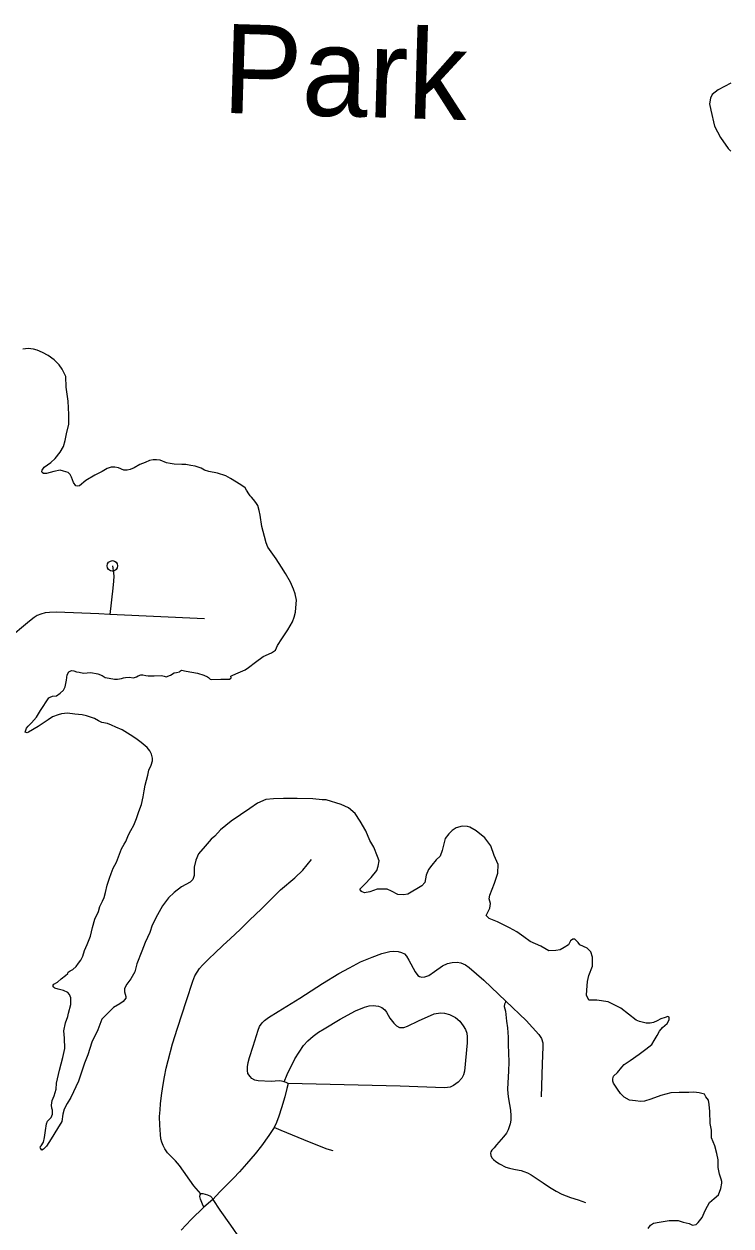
# Model space of a CAD drawing. Extents: x 653372 to 905732, y 627442 to 787275.
# Drawn here: x 725318 to 728673, y 734929 to 740630 of the extents above; entities that cross this region are included whole.
import ezdxf

# ---------------------------------------------------------------- set-up
doc = ezdxf.new("R2010")
doc.units = 0
for name, color, linetype in [('31', 7, 'Continuous'), ('45', 7, 'Continuous'), ('7', 7, 'Continuous'), ('9', 7, 'Continuous')]:
    doc.layers.add(name, color=color, linetype=linetype)

msp = doc.modelspace()

# ---------------------------------------------------------------- linework, layer by layer
at = {"layer": '31'}
for points in [[(725737.2, 738060), (725742.7, 738025.6), (725743.4, 738010.9), (725743.2, 737988.1), (725739.5, 737954.5), (725724.3, 737829.4)], [(726174.6, 737808.2), (725724.3, 737829.4), (725673.3, 737832.1), (725471.4, 737839.8), (725439.3, 737839.7), (725418, 737837.1), (725398.3, 737831.7), (725379.6, 737824.6), (725366.3, 737815.8), (725343.6, 737798), (725238.2, 737709.8)], [(726156.4, 735082.3), (726123.8, 735120.3), (726055.4, 735216.1), (726037.4, 735238.2), (725998.9, 735276.7), (725985.5, 735295.8), (725978.3, 735311.1), (725972.4, 735326.5), (725967.6, 735343), (725965.9, 735362.8), (725962.6, 735407.9), (725961.5, 735449.3), (725963.6, 735480.2), (725966.2, 735508.2), (725970.9, 735547.8), (725976.3, 735590.8), (725984, 735636.6), (725991.7, 735678.4), (726002.1, 735714.2), (726022.6, 735793.5), (726045.8, 735868.2), (726089.4, 735999.3), (726118.4, 736090), (726129, 736115.3), (726138.9, 736132.5), (726151.1, 736150.8), (726165, 736166.7), (726196.2, 736197.9), (726223.8, 736223.9), (726261.6, 736260.1), (726297.6, 736292.2), (726343.8, 736336.3), (726387.7, 736379.3), (726444.7, 736434.2), (726482, 736471), (726535.5, 736524.2), (726603, 736580.5), (726641.5, 736617.3), (726682.6, 736666.8)], [(726571.9, 735605.2), (726561.6, 735609.6), (726551.6, 735612.5), (726539.7, 735616.1), (726528, 735617), (726490.7, 735615.2), (726429.5, 735617.7), (726413.9, 735620.5), (726399.5, 735628.5), (726391.7, 735638.6), (726379.9, 735653), (726377.9, 735667), (726378.5, 735684.5), (726380.8, 735704.3), (726387.4, 735728.6), (726405.3, 735781.7), (726429.2, 735858.6), (726436.1, 735875.8), (726447.7, 735892.4), (726459.1, 735904.3), (726478.8, 735918.3), (726524.5, 735947.1), (726626.6, 736010.4), (726734.8, 736079.5), (726812.6, 736126.1), (726861.8, 736153.8), (726914.6, 736182), (726969.5, 736204.8), (727016, 736222.1), (727053.1, 736231.5), (727072.9, 736233.2), (727093.3, 736231.4), (727108.9, 736226.9), (727123.3, 736219.4), (727133.4, 736209.2), (727144.5, 736189.6), (727174.4, 736135.1), (727186.7, 736117.8), (727194.7, 736112.3), (727205.1, 736109.7), (727220.3, 736111.5), (727239.2, 736118), (727266.5, 736136.4), (727303.2, 736162.7), (727328.1, 736174.2), (727349.8, 736179.4), (727372.6, 736181), (727391.1, 736177), (727412.4, 736167.6), (727430.1, 736154.8), (727500.6, 736095), (727604.9, 735995.1), (727701.3, 735903.5), (727761.1, 735837.5), (727773.3, 735818.5), (727779.7, 735798.5), (727780.3, 735779.8), (727776.7, 735698.2), (727771.5, 735542.5)], [(727604.9, 735995.1), (727602.4, 735990.5), (727598.6, 735980.7), (727597.1, 735969.7), (727602.3, 735948.5), (727607.9, 735900), (727611.6, 735868.9), (727616.1, 735825.1), (727615.1, 735790.1), (727617.8, 735707.2), (727616.5, 735662.9), (727612.8, 735580), (727613.9, 735555.4), (727617.2, 735532), (727626.7, 735478.6), (727628.2, 735452.3), (727628.2, 735430.8), (727624.7, 735413.4), (727620.8, 735398.9), (727615.7, 735385.6), (727607.1, 735370.2), (727593.8, 735352.5), (727560, 735315), (727548.2, 735300.2), (727537.3, 735288.8), (727533.6, 735281.4), (727532.2, 735274.4), (727533.4, 735263.3), (727538.3, 735253.2), (727545.9, 735244.3), (727557.6, 735234.6), (727574.7, 735224.1), (727604, 735209), (727621.4, 735203.5), (727641.6, 735199.1), (727650.3, 735197.1), (727676.4, 735192.5), (727689.1, 735188.3), (727706.7, 735182), (727724.2, 735171.5), (727747.9, 735155.7), (727781.7, 735133.9), (727811.7, 735114.1), (727843.4, 735094.8), (727870.4, 735080.8), (727890, 735072.9), (727911.9, 735065), (727946.9, 735052.9), (727982, 735040.1)], [(726551.6, 735612.5), (726567.3, 735648.2), (726603.5, 735722.6), (726622.9, 735753.8), (726643.7, 735785.3), (726664.8, 735808), (726689.3, 735829.4), (726715.6, 735847.9), (726742.3, 735864), (726818.9, 735909.5), (726891.2, 735949.9), (726933.1, 735966.7), (726955.5, 735973.1), (726974.7, 735974.8), (727000.3, 735971.7), (727015.8, 735964.8), (727030.1, 735955.1), (727037.9, 735943.2), (727054, 735914.7), (727072.5, 735891.4), (727085.6, 735878.8), (727100.5, 735870.7), (727119.9, 735870.1), (727137.1, 735877.8), (727189.7, 735903), (727263.6, 735935.2), (727294, 735939.6), (727313.8, 735938.4), (727337.5, 735931.8), (727365.7, 735918.2), (727386.1, 735900.1), (727402.4, 735878.6), (727413, 735861.3), (727418.8, 735843.7), (727420.7, 735826.7), (727420.4, 735797.5), (727408.2, 735662.9), (727403.6, 735646.7), (727395, 735631.2), (727377.5, 735611), (727356.5, 735595.6), (727340.7, 735587.7), (727328.3, 735585.4), (727313.1, 735584.7), (727102.9, 735592.7), (726571.9, 735605.2)], [(726571.9, 735605.2), (726565.7, 735580.7), (726555.2, 735542.6), (726539, 735489.4), (726526.8, 735450.7), (726516.5, 735420.1), (726505.3, 735396.5), (726479.1, 735358.8), (726445.6, 735309.6), (726414.7, 735272.1), (726373.6, 735223.7), (726341.1, 735185.9), (726311.9, 735155.6), (726247.2, 735091), (726214.6, 735054.7), (726171.7, 735019.2), (726111.5, 734959.8), (726063.9, 734909.9)], [(726171.7, 735019.2), (726164.4, 735032.9), (726155.2, 735056.2), (726152.4, 735069.8), (726153.1, 735077), (726156.4, 735082.3), (726160.1, 735083.6), (726166.8, 735083.8), (726188.3, 735077.3), (726202.5, 735071), (726208.6, 735065), (726214.6, 735054.7)], [(726214.6, 735054.7), (726247.4, 735003.9), (726297.9, 734932.5), (726342.8, 734867.1)]]:
    msp.add_lwpolyline(points, dxfattribs=at)
msp.add_circle((725737.2, 738060), 25, dxfattribs=at)
at = {"layer": '45'}
msp.add_lwpolyline([(726784.2, 735285.5), (726756.5, 735293.9), (726672.9, 735326.7), (726538.1, 735381.5), (726505.3, 735396.5)], dxfattribs=at)
at = {"layer": '9'}
for points in [[(728672.8, 740349.1), (728611.7, 740317.6), (728583.8, 740296.1), (728575, 740279), (728570.8, 740251.8), (728577.4, 740221.5), (728594.9, 740144.9), (728622.3, 740091.9), (728659.6, 740040.3), (728672.8, 740027.1)], [(726610.9, 737897.9), (726603.8, 737927.1), (726596.5, 737949.8), (726582.2, 737982.4), (726558.9, 738023.7), (726540.2, 738053.2), (726514.6, 738093.1), (726490.2, 738126.5), (726475, 738148.7), (726466.9, 738169.9), (726459.8, 738199.1), (726446, 738246.6), (726438.3, 738301.2), (726434.5, 738322.3), (726427.3, 738346.3), (726418.3, 738360.3), (726407.2, 738375.2), (726397.3, 738386.3), (726391, 738392.3), (726384.8, 738401.2), (726374.4, 738418.9), (726367.5, 738430), (726351.2, 738440.6), (726326.3, 738457.3), (726297.9, 738474.1), (726275.1, 738487.8), (726235.9, 738499.6), (726194.1, 738508.1), (726174.7, 738513.8), (726159.1, 738523), (726130.4, 738532.5), (726109.5, 738536.8), (726085.7, 738541.1), (726066.2, 738541), (726030.7, 738542.8), (726012, 738546.2), (725994, 738548.2), (725963.9, 738560.7), (725946.6, 738563.4), (725931.4, 738563.1), (725913.2, 738560.1), (725892.6, 738550.5), (725867.7, 738541.1), (725839.9, 738524.6), (725821.6, 738517.9), (725807, 738514.7), (725791.8, 738514.4), (725766.8, 738525.3), (725749.5, 738528.7), (725732.1, 738528.5), (725712.3, 738521.9), (725688, 738508.1), (725653.4, 738490.3), (725610.7, 738465.5), (725581, 738440.3), (725571, 738437.7), (725563, 738439.4), (725552.6, 738455), (725542.6, 738481.3), (725537.1, 738493.1), (725527.3, 738503.5), (725505, 738510), (725489.9, 738513.4), (725459.3, 738507), (725424.3, 738497.9), (725410.5, 738497.6), (725404.1, 738502.2), (725402.8, 738508), (725404.5, 738514.5), (725412.9, 738528), (725445.4, 738550.9), (725465.5, 738569.9), (725489.6, 738598.9), (725504.9, 738625.9), (725513.1, 738654.6), (725519.8, 738686.4), (725529.8, 738731.7), (725530.4, 738777.3), (725527.3, 738841.2), (725518.4, 738907.4), (725516.3, 738958.2), (725499.3, 738993.4), (725485.4, 739014.1), (725460.8, 739037.4), (725432.4, 739057.8), (725405.3, 739072.3), (725379.6, 739083.3), (725362.3, 739088.1), (725337, 739090.3), (725311.6, 739087.5)], [(725780.1, 737525.8), (725790.3, 737529.8), (725799.1, 737531), (725817.2, 737531.9), (725837.4, 737529.9), (725852, 737533.8), (725860.2, 737539.3), (725871.9, 737543.3), (725882, 737543), (725896.4, 737539.7), (725907.2, 737538.6), (725936.2, 737539.2), (725969.9, 737539.7), (725983.6, 737537.1), (725992.9, 737534.6), (726012.7, 737541.3), (726029.7, 737552.4), (726041.4, 737554.9), (726055.2, 737557.4), (726059.7, 737563.1), (726064.9, 737565.8), (726087.2, 737561.5), (726141.2, 737550.5), (726171.4, 737542.3), (726187.8, 737534.6), (726193.5, 737530.8), (726199.1, 737524.8), (726200.5, 737522.6), (726209.9, 737521.6), (726252.6, 737523.2), (726292.5, 737523.5), (726299.1, 737527.6), (726300.6, 737529), (726300.7, 737531.2), (726299.3, 737533.4), (726299.4, 737536.3), (726308.3, 737542.5), (726334.7, 737553.3), (726367.7, 737567.6), (726382.5, 737578), (726415.9, 737603.8), (726452.9, 737630.2), (726491.8, 737647.9), (726511, 737661.1), (726521.1, 737681.8), (726540.9, 737714.5), (726569.7, 737757.1), (726592.5, 737794.1), (726600.5, 737817.1), (726606.2, 737840.1), (726609.6, 737879.8), (726610.9, 737897.9)], [(725821.3, 737258.6), (725782.9, 737283), (725754.3, 737295.4), (725732.9, 737304.8), (725713.6, 737312.6), (725687.6, 737317.7), (725671.9, 737325.4), (725652, 737336.2), (725638.3, 737340.9), (725614.7, 737348.9), (725594.5, 737353.8), (725558.4, 737356.4), (725523.8, 737361), (725496.2, 737359), (725479.4, 737354.4), (725453.7, 737343.6), (725432.3, 737329.7), (725385, 737297.8), (725339.3, 737270.9), (725332.6, 737267.5), (725324, 737270.7), (725324.9, 737276.4), (725329.7, 737290.1), (725337.2, 737299.3), (725352.9, 737315.5), (725376.9, 737343), (725396, 737374.3), (725435.4, 737434), (725441.3, 737438.2), (725453.1, 737442.1), (725472, 737444.5), (725489, 737455.6), (725505.3, 737470.3), (725513.8, 737486.7), (725519.8, 737517.7), (725522.7, 737543.7), (725531.1, 737557.2), (725542.9, 737564.1), (725554.4, 737562.3), (725566.6, 737558.3), (725579.6, 737555.7), (725600.5, 737551.5), (725634.6, 737554.8), (725667.7, 737547.3), (725689.3, 737540.8), (725703.5, 737531), (725721.4, 737526.8), (725747.4, 737523.2), (725761.9, 737522), (725780.1, 737525.8)], [(725740.8, 736627), (725756.8, 736654.1), (725766.3, 736680.6), (725779.7, 736718.6), (725793.4, 736740.7), (725801.1, 736753.5), (725812.9, 736785), (725824.4, 736805.7), (725838.9, 736829.9), (725852.1, 736861.4), (725863.2, 736894.4), (725875.1, 736928.8), (725883.4, 736964), (725888.7, 736993.6), (725893.1, 737020.3), (725905.4, 737067), (725909.7, 737090.8), (725921.3, 737115.1), (725927, 737135.2), (725928.1, 737148.9), (725922.8, 737166.5), (725914.7, 737183.4), (725902.8, 737198.2), (725873.8, 737223), (725849, 737241.1), (725821.3, 737258.6)], [(727333.7, 736789.1), (727317.1, 736766.4), (727302.4, 736710.3), (727292.9, 736683.1), (727273.5, 736666.3), (727252.5, 736640.8), (727237.3, 736619.5), (727226.4, 736593.8), (727219.6, 736557.8), (727206, 736542.2), (727139, 736503.7), (727118.6, 736499.9), (727091.1, 736502.2), (727061.2, 736517.6), (727041.2, 736526.9), (727022.3, 736527.5), (726993.4, 736526.9), (726959.7, 736514.8), (726933.4, 736509.8), (726919.1, 736516.1), (726912.2, 736526.4), (726933.2, 736549), (726964.6, 736582.8), (726991.7, 736615.3), (726998.1, 736635.4), (727003.2, 736661.4), (726995.1, 736681.9), (726977.6, 736725.9), (726958.2, 736756.9), (726939.4, 736803.8), (726913.2, 736849.6), (726889.7, 736885), (726857.2, 736912.1), (726822.8, 736927.6), (726751.1, 736949.9), (726732.3, 736950.5), (726688.9, 736954.7), (726613.7, 736957), (726548.5, 736957.5), (726502, 736954.5), (726465.8, 736952.7), (726426.1, 736935.1), (726389.2, 736910.1), (726300.8, 736849.1), (726250.4, 736808.5), (726223.4, 736777.5), (726205.6, 736763.5), (726177.1, 736731), (726145.5, 736694.3), (726133, 736664.3), (726124.8, 736631.2), (726125.1, 736592)], [(728223, 735905.4), (728150.5, 735961.7), (728090.6, 735992.5), (728035.8, 735999.9), (728006.9, 736000.8), (727998.2, 736001.1), (727987.3, 736024.6), (727988, 736047.8), (727992.1, 736088.2), (727998.8, 736117), (728016, 736161.4), (728015.9, 736204.9), (728007.9, 736229.8), (727991.1, 736247.7), (727955.3, 736263.2), (727948.4, 736273.6), (727931.5, 736290), (727922.8, 736290.3), (727911, 736282), (727901.7, 736263.4), (727881, 736249.5), (727861.9, 736238.5), (727841.5, 736236.2), (727808.1, 736234.3), (727769.7, 736255.8), (727719.7, 736279), (727689.9, 736300.2), (727655.8, 736324.4), (727621.6, 736342.8), (727564.6, 736372.1), (727525.9, 736387.7), (727511.8, 736401.2), (727522.7, 736424), (727528.8, 736436.9), (727530.9, 736458.6), (727525.8, 736480.5), (727529.2, 736497.7), (727549.8, 736555.1), (727565.7, 736602.4), (727568.4, 736644.4), (727549.4, 736687), (727533.4, 736732.4), (727504.1, 736769.5), (727463.1, 736804.1), (727433.2, 736820.9), (727421.7, 736824.1), (727397.1, 736824.9), (727369.3, 736817), (727350.1, 736804.6), (727333.7, 736789.1)], [(725445.9, 735444.5), (725452.2, 735460.2), (725452.8, 735479.1), (725450.1, 735487.8), (725447.7, 735502.4), (725451.2, 735524), (725460.6, 735546.9), (725470.3, 735578.5), (725472.5, 735606), (725486, 735667.9), (725502.3, 735728.3), (725510.8, 735771.5), (725509.4, 735819.4), (725507.5, 735854.2), (725514.5, 735893.1), (725525.5, 735923.2), (725528.9, 735939.1), (725539.5, 735980), (725539.7, 736011.2), (725534.4, 736027.3), (725526, 736037), (725505.3, 736046.3), (725480.1, 736052.1), (725463.6, 736057), (725459.4, 736062.2), (725454.6, 736068.8), (725459.8, 736075.9), (725476.8, 736085.5), (725493.9, 736101), (725515.4, 736117), (725525.1, 736127.6), (725527.5, 736133.3), (725536.3, 736138.8), (725548.9, 736145.7), (725564.5, 736160.4), (725575.8, 736175.3), (725587.1, 736190.2), (725597.1, 736208.7), (725604.4, 736236.1), (725617.6, 736264.8), (725632.6, 736304.2), (725642.5, 736344.5), (725653.1, 736384), (725670.8, 736421.2), (725678.1, 736444.2), (725689.7, 736470.6), (725698.9, 736487.7), (725704.7, 736511.5), (725712.2, 736545.3), (725722.7, 736578.3), (725731.3, 736601.2), (725740.8, 736627)], [(726125.1, 736592), (726118.7, 736571.9), (726106.7, 736560.7), (726065.5, 736537.3), (726029.9, 736510.8), (726003.1, 736485.6), (725974.4, 736447.3), (725951.4, 736404.5), (725925.3, 736356), (725915.6, 736321.5), (725892.4, 736274.4), (725876.7, 736232.8), (725853.2, 736172.7), (725843.4, 736135.3), (725824.9, 736101.1), (725805.3, 736075.6), (725794.6, 736055.6), (725794.1, 736039.7), (725800.7, 736017.8), (725800.5, 736010.5), (725788.4, 735993.5), (725772.1, 735982.4), (725742.6, 735965.9), (725717.3, 735940.6), (725687.4, 735909.6), (725668.5, 735859.4), (725639.2, 735800.9), (725621.4, 735740.7), (725604.3, 735702), (725575.7, 735615.9), (725540, 735538.8), (725521.8, 735510.3), (725508, 735483.2), (725501.5, 735460.2), (725497.5, 735425.6), (725476.2, 735391.4), (725447.2, 735343), (725424.4, 735307.5), (725411, 735293.4), (725402.2, 735289.3), (725396.6, 735298.2), (725393.9, 735304), (725398.4, 735309.7), (725410.5, 735326.7), (725415.6, 735349.8), (725419.5, 735383), (725424.7, 735413.2), (725429.5, 735426.1), (725439.9, 735437.4), (725445.9, 735444.5)], [(728280.4, 734917.7), (728290.4, 734933.2), (728304.9, 734942.3), (728332, 734947.8), (728379.8, 734955.9), (728422.5, 734954.6), (728446, 734947.6), (728474.3, 734940.4), (728489.9, 734933.6), (728507.4, 734936.2), (728517.2, 734945.4), (728535.4, 734970.2), (728550.6, 735003), (728560.7, 735023.3), (728570.8, 735040.4), (728593.5, 735060.4), (728613, 735077.2), (728625, 735106.6), (728628.9, 735131.8), (728629.2, 735139.7), (728626.3, 735150.9), (728617.6, 735174.9), (728612.2, 735206.8), (728611.7, 735243.2), (728606.3, 735273.5), (728596.3, 735310.2), (728580, 735347.1), (728581.1, 735383.5), (728574.1, 735415.1), (728572.6, 735472.2), (728568.9, 735505.6), (728566.3, 735526.2), (728554.2, 735542.4), (728546.6, 735553.8), (728534, 735557.3), (728521.5, 735560.9), (728496.2, 735564.8), (728472.4, 735562.3), (728426.5, 735562.1), (728386.8, 735560.1), (728340.6, 735548.9), (728292.5, 735531.3), (728262.1, 735521.1), (728243.1, 735520.1), (728219.4, 735522.4), (728191, 735526.4), (728166.1, 735539.8), (728149.2, 735557.8), (728134, 735578.8), (728127.9, 735588.5), (728115.8, 735606.3), (728112.9, 735615.9), (728111.7, 735627), (728115.2, 735639.6), (728134.8, 735658), (728154.5, 735682.8), (728166, 735695.1), (728195.1, 735714.8), (728237.2, 735745), (728269.5, 735767.8), (728297.1, 735790.7), (728308.8, 735809.4), (728322.2, 735832.7), (728333.8, 735853), (728348.6, 735870), (728369.8, 735889.9), (728379.8, 735907), (728380.1, 735914.9), (728380.2, 735919.7), (728372.4, 735923.1), (728361.2, 735918.7), (728340.4, 735911.4), (728322.7, 735902.4), (728305, 735895), (728289.1, 735890.7), (728270.1, 735891.3), (728238.6, 735898.6), (728223, 735905.4)]]:
    msp.add_lwpolyline(points, dxfattribs=at)

# ---------------------------------------------------------------- texts
at = {"layer": '7'}
msp.add_text('Park', height=422.4, rotation=358.28, dxfattribs=at).set_placement((726255.4, 740209.1))

doc.saveas('drawing.dxf')
